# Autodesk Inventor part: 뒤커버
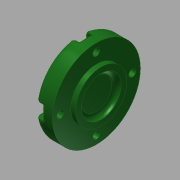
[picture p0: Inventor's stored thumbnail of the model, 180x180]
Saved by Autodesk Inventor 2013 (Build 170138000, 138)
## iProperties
Created: 2015-11
Part Number: 뒤커버
Material: 알루미늄 6061
Document SubType Name: Modeling
Designer: mduedu
Density: 1 g/cm^3
Author: mduedu
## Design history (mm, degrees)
sketch "스케치1"
  geometry: L1 (-7, 0)-(7, 0); L2 (-7, 0)-(-7, 27.5); L3 (-7, 27.5)-(4, 27.5); L4 (4, 27.5)-(4, 16); L5 (4, 16)-(7, 16); L6 (7, 16)-(7, 0); 2 further points
  constraints: 12 end point, 3 perpendicular, 2 parallel, 1 coincident, 1 horizontal, 1 midpoint
  dimensions: "d0" = 14 distance of L1.start L1.end; "d1" = 55 diameter of L3 L1; "d2" = 3 distance of L4.end L5.end; "d3" = 32 diameter of L5 L1
revolve "회전1" sketch "스케치1" stored, may be unused: angle "d4" = 90 deg
hole "구멍1" diameter "d7" = 25; stored, may be unused: countersink angle "d11" = 90 deg, drill point angle "d13" = 0 deg; dims "d5" = 10, "d6" = 10, "d8" = 6, "d9" = 4, "d10" = 2, "d12" = 3
fillet "모깎기2" dims "d36" = 3
fillet "모깎기3" dims "d37" = 3
sketch "스케치2" dims "d39" = 45
  geometry: C1 r 12.846 at (0, 0) reference; C2 r 24.5 at (0, 0) reference; 6 further points
  constraints: 2 vertical alignment, 1 coincident, 7 other
  dimensions: "d42" = 360 deg dimension on point (0, 0) point (0, 22.5) (derived)
sketch "스케치3"
  geometry: 8 further points
  constraints: 4 coincident
hole "구멍4" sketch "스케치3" at (-22.5, 0), (0, -22.5), (22.5, 0), (0, 22.5) diameter "d44" = 4.5; stored, may be unused: countersink angle "d48" = 90 deg, drill point angle "d50" = 0 deg; dims "d45" = 6, "d46" = 8, "d47" = 4.6, "d49" = 8
sketch "스케치4"
  geometry: L1 (-4, 0)-(-4, -4.708); L2 (4, 0)-(4, -4.708); A1 r 4 centre (0, 0) between (-4, 0) and (4, 0) reference; A2 r 27.5 centre (0, 22.5) between (-4, -4.708) and (4, -4.708) reference; 3 further points
  constraints: 4 end point, 4 point on circle, 2 tangent, 1 parallel, 1 vertical
extrude "돌출1" cut sketch "스케치4" stored distance "d51" = 0; taper "d52" = 0 deg
fillet "모깎기5" dims "d56" = 0.3
fillet "모깎기6" dims "d57" = 1
node "솔리드1"
pattern_circular "원형 패턴1" dims angle "d54" = 360 deg
